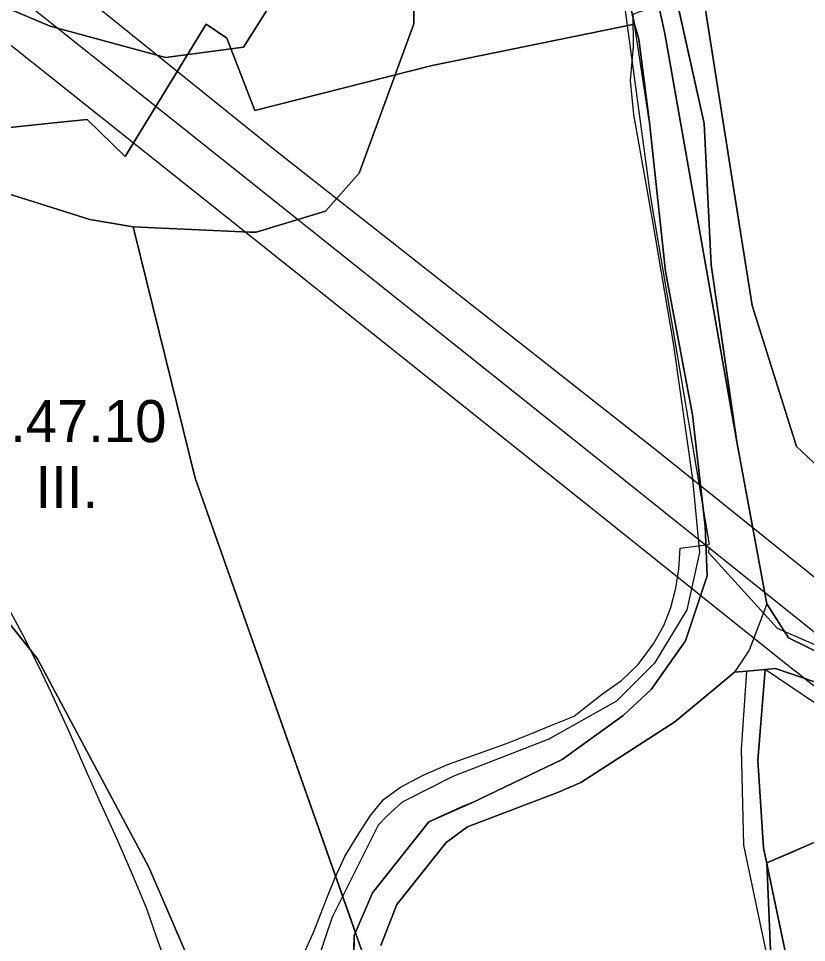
# Model space of a CAD drawing. Extents: x -690419 to -685080, y -987825 to -981190.
# Drawn here: x -687235.5 to -687048.1, y -987168.9 to -986949.2 of the extents above; entities that cross this region are included whole.
import ezdxf

# ---------------------------------------------------------------- set-up
doc = ezdxf.new("R2010")
doc.units = 0
for name, color, linetype in [('BPEJ (S) - hranice', 7, 'Continuous'), ('BPEJ (S) - kód', 7, 'Continuous'), ('BPEJ I-II ochrana', 7, 'Continuous'), ('Elektro VN 35 nadzemní (S)', 7, 'Continuous'), ('OP elektro VN (S)', 7, 'Continuous'), ('Plochy smíšené nezastavěného území všeobecné MU (S)', 7, 'Continuous'), ('Plochy veřejná prostranství všeobecná PU (S)', 7, 'Continuous'), ('Plochy zemědělské všeobecné AU (S)', 7, 'Continuous'), ('Regulační bloky STABILIZOVANÉ (S)', 7, 'Continuous'), ('Spoje - komunikační vedení bez rozlišení provozovanál (S)', 7, 'Continuous'), ('Trasy cykloturistické (S)', 7, 'Continuous'), ('Trasy turistické (S)', 7, 'Continuous'), ('Vodovodní řady přiváděcí (S)', 7, 'Continuous')]:
    doc.layers.add(name, color=color, linetype=linetype)

msp = doc.modelspace()

# ---------------------------------------------------------------- linework, layer by layer
at = {"layer": 'BPEJ (S) - hranice'}
for points in [[(-687151, -987179), (-687193.5, -987058.5), (-687207.88, -987000), (-687208.19, -986998.75), (-687194.34, -986999.37), (-687180.5, -987000), (-687179, -987000), (-687162.5, -986995), (-687154.5, -986986), (-687141.5, -986950.5), (-687141, -986905.5), (-687147, -986860.5), (-687168.5, -986791), (-687205.5, -986705), (-687244, -986635.5)], [(-687244, -986635.5), (-687205.5, -986705), (-687168.5, -986791), (-687147, -986860.5), (-687141, -986905.5), (-687141.5, -986950.5), (-687154.5, -986986), (-687162.5, -986995), (-687179, -987000), (-687180.5, -987000), (-687194.34, -986999.37), (-687208.19, -986998.75), (-687218.5, -986997), (-687242.5, -986989.5)], [(-687273, -986932), (-687228, -986951), (-687200.5, -986958.5), (-687182, -986956), (-687176, -986946.5), (-687178, -986933), (-687195.5, -986898), (-687200.5, -986888.5), (-687256.5, -986707)], [(-687238, -986892.5), (-687195.5, -986898), (-687178, -986933), (-687176, -986946.5), (-687182, -986956), (-687200.5, -986958.5), (-687228, -986951), (-687273, -986932)], [(-686944.5, -986926), (-686946.5, -986962), (-686946.68, -987000), (-686947, -987070), (-686950.5, -987088), (-686967.5, -987086), (-687024.5, -987071), (-687033, -987067.5), (-687050.5, -987051), (-687061, -987017.5), (-687063.76, -987000), (-687074.5, -986932)], [(-687074.5, -986932), (-687063.76, -987000), (-687061, -987017.5), (-687050.5, -987051), (-687033, -987067.5), (-687024.5, -987071), (-687022, -987099), (-687015, -987112), (-686990, -987129), (-686932.5, -987151.5), (-686936.25, -987205.68)], [(-687242.5, -986989.5), (-687218.5, -986997), (-687208.19, -986998.75), (-687207.88, -987000), (-687193.5, -987058.5), (-687151, -987179)], [(-687249, -987079), (-687231, -987101.5), (-687204.5, -987151), (-687189, -987187)], [(-687189, -987187), (-687204.5, -987151), (-687231, -987101.5), (-687249, -987079)], [(-687056.5, -987174.58), (-687057.5, -987150), (-687046, -987145), (-686988.5, -987157), (-686969, -987168.5), (-686950, -987186)], [(-686950, -987186), (-686969, -987168.5), (-686988.5, -987157), (-687046, -987145), (-687057.5, -987150), (-687056.5, -987174.58)]]:
    msp.add_lwpolyline(points, dxfattribs=at)
at = {"layer": 'BPEJ I-II ochrana'}
for p, q in [((-687089, -986950.57), (-687098.46, -986908.8)), ((-687079.35, -986943.19), (-687072.43, -986974.16)), ((-687087.97, -986954.16), (-687089, -986950.57)), ((-687085.46, -986973.92), (-687087.97, -986954.16)), ((-687081.65, -987009.35), (-687085.46, -986973.92)), ((-687072.43, -986974.16), (-687070.74, -987007.79)), ((-687070.74, -987007.79), (-687064.71, -987049.91)), ((-687075.25, -987043.43), (-687081.65, -987009.35)), ((-687072.23, -987069.95), (-687075.25, -987043.43)), ((-687064.71, -987049.91), (-687057.51, -987088.37)), ((-687071.71, -987081.71), (-687072.23, -987069.95)), ((-687076.84, -987097.19), (-687071.71, -987081.71)), ((-687057.51, -987088.37), (-687052.41, -987096.45)), ((-687052.41, -987096.45), (-687043.38, -987100.92)), ((-687085.03, -987108.79), (-687076.84, -987097.19)), ((-687065.23, -987104.62), (-687069.67, -987108.38)), ((-687062.27, -987104.38), (-687065.23, -987104.62)), ((-687063.59, -987122.98), (-687062.27, -987104.38)), ((-687057.95, -987104.02), (-687059.69, -987125.65)), ((-687031.33, -987121.96), (-687057.95, -987104.02)), ((-687091.67, -987114.95), (-687085.03, -987108.79)), ((-687069.67, -987108.38), (-687079.4, -987116.46)), ((-687106.18, -987125.43), (-687091.67, -987114.95)), ((-687079.4, -987116.46), (-687101.73, -987130.92)), ((-687063.04, -987145.76), (-687063.59, -987122.98)), ((-687127.72, -987135.74), (-687106.18, -987125.43)), ((-687059.69, -987125.65), (-687058.33, -987146.42)), ((-687101.73, -987130.92), (-687107.05, -987133.19)), ((-687107.05, -987133.19), (-687128.7, -987141.41)), ((-687137.9, -987140.22), (-687129.74, -987136.48)), ((-687129.74, -987136.48), (-687127.72, -987135.74)), ((-687151.34, -987157.1), (-687137.9, -987140.22)), ((-687128.7, -987141.41), (-687133.81, -987145.13)), ((-687133.81, -987145.13), (-687145.5, -987159.88)), ((-687057.29, -987172.87), (-687063.04, -987145.76)), ((-687058.33, -987146.42), (-687057.48, -987150.46)), ((-687057.5, -987150), (-687051.94, -987147.58)), ((-687057.48, -987150.46), (-687057.5, -987150)), ((-687155.38, -987166.57), (-687151.34, -987157.1)), ((-687145.5, -987159.88), (-687149.31, -987169.64))]:
    msp.add_line(p, q, dxfattribs=at)
for points in [[(-687141, -986905.5), (-687141.5, -986950.5), (-687145.94, -986962.62)], [(-687145.94, -986962.62), (-687154.5, -986986), (-687162.5, -986995), (-687179, -987000), (-687180.5, -987000), (-687194.34, -986999.37), (-687208.19, -986998.75), (-687207.88, -987000), (-687193.5, -987058.5), (-687155.38, -987166.57)], [(-687051.94, -987147.58), (-687046, -987145), (-687033.03, -987147.71)]]:
    msp.add_lwpolyline(points, dxfattribs=at)
at = {"layer": 'Elektro VN 35 nadzemní (S)'}
msp.add_lwpolyline([(-687044.68, -987096.41), (-687089.26, -987060.74), (-687180.2, -986988.23), (-687272.01, -986915.09), (-687345.55, -986856.07), (-687424.59, -986793.57), (-687400.71, -986748.73), (-687400.48, -986748.73), (-687400.48, -986748.81)], dxfattribs=at)
at = {"layer": 'OP elektro VN (S)'}
for points in [[(-688231.26, -985362.69), (-688140.91, -985333.4), (-688050.6, -985304.66), (-687926.78, -985265.47), (-687889.09, -985253.55), (-687783.25, -985486.14), (-687655.15, -985766.87), (-687464.28, -985986.39), (-687075.22, -986433.52), (-686939.38, -986589.57), (-686741.02, -986817.05), (-686769.51, -986926.18), (-686773.44, -986930.55), (-686967.58, -987146.08), (-686995.86, -987122.7), (-687037.52, -987089.1), (-687083.41, -987052.28), (-687174.55, -986980.54), (-687265.93, -986906.92), (-687339.37, -986847.5), (-687412.5, -986789.56), (-687406.22, -986778.12)], [(-687422.93, -986769.17), (-687433.42, -986788.87), (-687434.1, -986790.47), (-687434.49, -986792.16), (-687434.59, -986793.89), (-687434.38, -986795.62), (-687433.88, -986797.28), (-687433.1, -986798.83), (-687432.06, -986800.22), (-687430.8, -986801.41), (-687351.78, -986863.89), (-687278.26, -986922.9), (-687186.43, -986996.05), (-687095.5, -987068.56), (-687050.93, -987104.22), (-687050.91, -987104.23)], [(-687050.91, -987104.23), (-687050.9, -987104.24), (-687008.22, -987138.15), (-686980.45, -987160.36)]]:
    msp.add_lwpolyline(points, dxfattribs=at)
at = {"layer": 'Plochy smíšené nezastavěného území všeobecné MU (S)'}
msp.add_lwpolyline([(-687064.71, -987049.91), (-687081.8, -986952.81), (-687097.31, -986882.03), (-687100.79, -986858.01), (-687105.29, -986824.57), (-687109.25, -986799.46), (-687102.67, -986798.7), (-687068.39, -986793.35), (-687049.96, -986854.98), (-687097.68, -986857.59), (-687097.65, -986861.02), (-687089.57, -986859.96), (-687088.88, -986889.77), (-687086.04, -986905.54), (-687079.35, -986943.19), (-687072.43, -986974.16), (-687070.74, -987007.79)], close=True, dxfattribs=at)
for points in [[(-687238.33, -986902.04), (-687202.07, -986901.51), (-687198.86, -986901.11), (-687195.86, -986900.35), (-687140.12, -986891.8), (-687134.26, -986917.02), (-687098.46, -986908.8), (-687089, -986950.57), (-687125.45, -986958), (-687137.1, -986960.37), (-687179.27, -986971.1), (-687185.91, -986953.93), (-687190.89, -986950.58), (-687210.15, -986982.01), (-687219.17, -986973.2), (-687225.5, -986973.87), (-687238.33, -986975.22)], [(-687052.28, -987175.23), (-687058.33, -987146.42), (-687059.69, -987125.65), (-687057.95, -987104.02), (-687055.46, -987103.82), (-687046.24, -987106.93), (-687031.65, -987113.14), (-687030.67, -987113.56), (-686938.13, -987152.9), (-686933.49, -987154.73), (-686905.86, -987166.25), (-686904.51, -987166.69), (-686905.7, -987172.32)]]:
    msp.add_lwpolyline(points, dxfattribs=at)
at = {"layer": 'Plochy veřejná prostranství všeobecná PU (S)'}
for p, q in [((-687097.31, -986882.03), (-687081.8, -986952.81)), ((-687089, -986950.57), (-687098.46, -986908.8)), ((-687087.97, -986954.16), (-687089, -986950.57)), ((-687085.46, -986973.92), (-687087.97, -986954.16)), ((-687081.8, -986952.81), (-687064.71, -987049.91)), ((-687081.65, -987009.35), (-687085.46, -986973.92)), ((-687075.25, -987043.43), (-687081.65, -987009.35)), ((-687072.23, -987069.95), (-687075.25, -987043.43)), ((-687064.71, -987049.91), (-687057.51, -987088.37)), ((-687071.71, -987081.71), (-687072.23, -987069.95)), ((-687076.84, -987097.19), (-687071.71, -987081.71)), ((-687057.51, -987088.37), (-687052.41, -987096.45)), ((-687052.41, -987096.45), (-687043.38, -987100.92)), ((-687085.03, -987108.79), (-687076.84, -987097.19)), ((-687065.23, -987104.62), (-687069.67, -987108.38)), ((-687062.27, -987104.38), (-687065.23, -987104.62)), ((-687057.95, -987104.02), (-687062.27, -987104.38)), ((-687055.46, -987103.82), (-687057.95, -987104.02)), ((-687046.24, -987106.93), (-687055.46, -987103.82)), ((-687091.67, -987114.95), (-687085.03, -987108.79)), ((-687069.67, -987108.38), (-687079.4, -987116.46)), ((-687106.18, -987125.43), (-687091.67, -987114.95)), ((-687079.4, -987116.46), (-687101.73, -987130.92)), ((-687127.72, -987135.74), (-687106.18, -987125.43)), ((-687101.73, -987130.92), (-687107.05, -987133.19)), ((-687107.05, -987133.19), (-687128.7, -987141.41)), ((-687137.9, -987140.22), (-687129.74, -987136.48)), ((-687129.74, -987136.48), (-687127.72, -987135.74)), ((-687151.34, -987157.1), (-687137.9, -987140.22)), ((-687128.7, -987141.41), (-687133.81, -987145.13)), ((-687133.81, -987145.13), (-687145.5, -987159.88)), ((-687155.68, -987167.27), (-687151.34, -987157.1)), ((-687145.5, -987159.88), (-687149.31, -987169.64)), ((-687156.34, -987207.91), (-687155.68, -987167.27))]:
    msp.add_line(p, q, dxfattribs=at)
at = {"layer": 'Plochy zemědělské všeobecné AU (S)'}
for p, q in [((-687069.67, -987108.38), (-687065.23, -987104.62)), ((-687065.23, -987104.62), (-687062.27, -987104.38)), ((-687062.27, -987104.38), (-687057.95, -987104.02)), ((-687057.95, -987104.02), (-687059.69, -987125.65)), ((-687079.4, -987116.46), (-687069.67, -987108.38)), ((-687101.73, -987130.92), (-687079.4, -987116.46)), ((-687059.69, -987125.65), (-687058.33, -987146.42)), ((-687107.05, -987133.19), (-687101.73, -987130.92)), ((-687128.7, -987141.41), (-687107.05, -987133.19)), ((-687133.81, -987145.13), (-687128.7, -987141.41)), ((-687145.5, -987159.88), (-687133.81, -987145.13)), ((-687058.33, -987146.42), (-687052.28, -987175.23)), ((-687149.31, -987169.64), (-687145.5, -987159.88))]:
    msp.add_line(p, q, dxfattribs=at)
for points in [[(-686936.47, -986938.56), (-686948.57, -987004.84), (-686941.32, -987008.49), (-686941.23, -987025.06), (-686947.38, -987090.16), (-686929.71, -987120.98), (-686926.56, -987106.84), (-686895.85, -987125.85), (-686897.44, -987133.18), (-686903.38, -987161.33), (-686904.48, -987160.91), (-686933.38, -987148.4), (-686935.6, -987147.41), (-687028.95, -987107.87), (-687030.06, -987107.34), (-687031.74, -987106.53), (-687043.38, -987100.92), (-687052.41, -987096.45), (-687057.51, -987088.37), (-687064.71, -987049.91), (-687070.74, -987007.79), (-687072.43, -986974.16), (-687079.35, -986943.19)], [(-687238.33, -986975.22), (-687225.5, -986973.87), (-687219.17, -986973.2), (-687210.15, -986982.01), (-687190.89, -986950.58), (-687185.91, -986953.93), (-687179.27, -986971.1), (-687137.1, -986960.37), (-687125.45, -986958), (-687089, -986950.57), (-687087.97, -986954.16), (-687085.46, -986973.92), (-687081.65, -987009.35), (-687075.25, -987043.43), (-687072.23, -987069.95), (-687071.71, -987081.71), (-687076.84, -987097.19), (-687085.03, -987108.79), (-687091.67, -987114.95), (-687106.18, -987125.43), (-687127.72, -987135.74), (-687129.74, -987136.48), (-687137.9, -987140.22), (-687151.34, -987157.1), (-687155.68, -987167.27), (-687156.34, -987207.91)]]:
    msp.add_lwpolyline(points, dxfattribs=at)
at = {"layer": 'Regulační bloky STABILIZOVANÉ (S)'}
for p, q in [((-687097.31, -986882.03), (-687081.8, -986952.81)), ((-687089, -986950.57), (-687098.46, -986908.8)), ((-687087.97, -986954.16), (-687089, -986950.57)), ((-687085.46, -986973.92), (-687087.97, -986954.16)), ((-687081.8, -986952.81), (-687064.71, -987049.91)), ((-687081.65, -987009.35), (-687085.46, -986973.92)), ((-687075.25, -987043.43), (-687081.65, -987009.35)), ((-687072.23, -987069.95), (-687075.25, -987043.43)), ((-687064.71, -987049.91), (-687057.51, -987088.37)), ((-687071.71, -987081.71), (-687072.23, -987069.95)), ((-687076.84, -987097.19), (-687071.71, -987081.71)), ((-687057.51, -987088.37), (-687052.41, -987096.45)), ((-687052.41, -987096.45), (-687043.38, -987100.92)), ((-687085.03, -987108.79), (-687076.84, -987097.19)), ((-687069.67, -987108.38), (-687065.23, -987104.62)), ((-687065.23, -987104.62), (-687069.67, -987108.38)), ((-687065.23, -987104.62), (-687062.27, -987104.38)), ((-687062.27, -987104.38), (-687065.23, -987104.62)), ((-687062.27, -987104.38), (-687057.95, -987104.02)), ((-687057.95, -987104.02), (-687062.27, -987104.38)), ((-687057.95, -987104.02), (-687059.69, -987125.65)), ((-687055.46, -987103.82), (-687057.95, -987104.02)), ((-687046.24, -987106.93), (-687055.46, -987103.82)), ((-687091.67, -987114.95), (-687085.03, -987108.79)), ((-687079.4, -987116.46), (-687069.67, -987108.38)), ((-687069.67, -987108.38), (-687079.4, -987116.46)), ((-687106.18, -987125.43), (-687091.67, -987114.95)), ((-687101.73, -987130.92), (-687079.4, -987116.46)), ((-687079.4, -987116.46), (-687101.73, -987130.92)), ((-687127.72, -987135.74), (-687106.18, -987125.43)), ((-687059.69, -987125.65), (-687058.33, -987146.42)), ((-687107.05, -987133.19), (-687101.73, -987130.92)), ((-687101.73, -987130.92), (-687107.05, -987133.19)), ((-687128.7, -987141.41), (-687107.05, -987133.19)), ((-687107.05, -987133.19), (-687128.7, -987141.41)), ((-687137.9, -987140.22), (-687129.74, -987136.48)), ((-687129.74, -987136.48), (-687127.72, -987135.74)), ((-687151.34, -987157.1), (-687137.9, -987140.22)), ((-687133.81, -987145.13), (-687128.7, -987141.41)), ((-687128.7, -987141.41), (-687133.81, -987145.13)), ((-687145.5, -987159.88), (-687133.81, -987145.13)), ((-687133.81, -987145.13), (-687145.5, -987159.88)), ((-687058.33, -987146.42), (-687052.28, -987175.23)), ((-687155.68, -987167.27), (-687151.34, -987157.1)), ((-687149.31, -987169.64), (-687145.5, -987159.88)), ((-687145.5, -987159.88), (-687149.31, -987169.64)), ((-687156.34, -987207.91), (-687155.68, -987167.27))]:
    msp.add_line(p, q, dxfattribs=at)
msp.add_lwpolyline([(-687064.71, -987049.91), (-687081.8, -986952.81), (-687097.31, -986882.03), (-687100.79, -986858.01), (-687105.29, -986824.57), (-687109.25, -986799.46), (-687102.67, -986798.7), (-687068.39, -986793.35), (-687049.96, -986854.98), (-687097.68, -986857.59), (-687097.65, -986861.02), (-687089.57, -986859.96), (-687088.88, -986889.77), (-687086.04, -986905.54), (-687079.35, -986943.19), (-687072.43, -986974.16), (-687070.74, -987007.79)], close=True, dxfattribs=at)
for points in [[(-687238.33, -986902.04), (-687202.07, -986901.51), (-687198.86, -986901.11), (-687195.86, -986900.35), (-687140.12, -986891.8), (-687134.26, -986917.02), (-687098.46, -986908.8), (-687089, -986950.57), (-687125.45, -986958), (-687137.1, -986960.37), (-687179.27, -986971.1), (-687185.91, -986953.93), (-687190.89, -986950.58), (-687210.15, -986982.01), (-687219.17, -986973.2), (-687225.5, -986973.87), (-687238.33, -986975.22)], [(-686936.47, -986938.56), (-686948.57, -987004.84), (-686941.32, -987008.49), (-686941.23, -987025.06), (-686947.38, -987090.16), (-686929.71, -987120.98), (-686926.56, -987106.84), (-686895.85, -987125.85), (-686897.44, -987133.18), (-686903.38, -987161.33), (-686904.48, -987160.91), (-686933.38, -987148.4), (-686935.6, -987147.41), (-687028.95, -987107.87), (-687030.06, -987107.34), (-687031.74, -987106.53), (-687043.38, -987100.92), (-687052.41, -987096.45), (-687057.51, -987088.37), (-687064.71, -987049.91), (-687070.74, -987007.79), (-687072.43, -986974.16), (-687079.35, -986943.19)], [(-687238.33, -986975.22), (-687225.5, -986973.87), (-687219.17, -986973.2), (-687210.15, -986982.01), (-687190.89, -986950.58), (-687185.91, -986953.93), (-687179.27, -986971.1), (-687137.1, -986960.37), (-687125.45, -986958), (-687089, -986950.57), (-687087.97, -986954.16), (-687085.46, -986973.92), (-687081.65, -987009.35), (-687075.25, -987043.43), (-687072.23, -987069.95), (-687071.71, -987081.71), (-687076.84, -987097.19), (-687085.03, -987108.79), (-687091.67, -987114.95), (-687106.18, -987125.43), (-687127.72, -987135.74), (-687129.74, -987136.48), (-687137.9, -987140.22), (-687151.34, -987157.1), (-687155.68, -987167.27), (-687156.34, -987207.91)], [(-687052.28, -987175.23), (-687058.33, -987146.42), (-687059.69, -987125.65), (-687057.95, -987104.02), (-687055.46, -987103.82), (-687046.24, -987106.93), (-687031.65, -987113.14), (-687030.67, -987113.56), (-686938.13, -987152.9), (-686933.49, -987154.73), (-686905.86, -987166.25), (-686904.51, -987166.69), (-686905.7, -987172.32)]]:
    msp.add_lwpolyline(points, dxfattribs=at)
at = {"layer": 'Spoje - komunikační vedení bez rozlišení provozovanál (S)'}
for points in [[(-687134.78, -986558.12), (-687128.55, -986596.29), (-687121.87, -986632.23), (-687116.14, -986666.2), (-687116.24, -986675.79), (-687122.7, -986687.4), (-687120.3, -986718.33), (-687117.95, -986746.91), (-687112.46, -986783.6), (-687110.33, -986797.3), (-687107.08, -986821.56), (-687102.66, -986850.7), (-687097.67, -986883.59), (-687093.49, -986909.08), (-687089.93, -986925.78), (-687083.88, -986946.25), (-687087.97, -986947.72), (-687089.42, -986948.25), (-687089.31, -986955.87)], [(-687089.31, -986955.87), (-687090.05, -986963.93), (-687089.23, -986972.08), (-687084.78, -986997), (-687079.71, -987026.92), (-687075.24, -987058.78), (-687073.58, -987076.2), (-687076.54, -987089.84), (-687084.23, -987102.52), (-687093.27, -987111.55), (-687109.34, -987120.61), (-687132.23, -987129.5), (-687144.29, -987135.59), (-687147.81, -987138.83), (-687149.94, -987141.05), (-687160.87, -987162.92), (-687169.9, -987189.61)]]:
    msp.add_lwpolyline(points, dxfattribs=at)
at = {"layer": 'Trasy cykloturistické (S)'}
msp.add_lwpolyline([(-687156.34, -987207.91), (-687155.68, -987167.27), (-687151.34, -987157.1), (-687137.9, -987140.22), (-687127.72, -987135.74), (-687106.18, -987125.43), (-687091.67, -987114.95), (-687085.03, -987108.79), (-687076.84, -987097.19), (-687071.71, -987081.71), (-687072.23, -987069.95), (-687075.25, -987043.43), (-687081.65, -987009.35), (-687085.46, -986973.92), (-687089, -986950.57), (-687098.46, -986908.8)], dxfattribs=at)
at = {"layer": 'Trasy turistické (S)'}
msp.add_lwpolyline([(-687148.24, -986515.1), (-687133.5, -986598.3), (-687124.79, -986663.8), (-687121.11, -986707.42), (-687118.1, -986714.38), (-687115.43, -986735.93), (-687117.23, -986748.83), (-687105.29, -986824.57), (-687097.31, -986882.03), (-687081.8, -986952.81), (-687064.71, -987049.91), (-687057.51, -987088.37), (-687058.74, -987091.61), (-687061.71, -987099.42), (-687065.23, -987104.62), (-687069.67, -987108.38), (-687079.4, -987116.46), (-687101.73, -987130.92), (-687107.05, -987133.19), (-687128.7, -987141.41), (-687133.81, -987145.13), (-687145.5, -987159.88), (-687149.31, -987169.64)], dxfattribs=at)
at = {"layer": 'Vodovodní řady přiváděcí (S)'}
for points in [[(-687071.2, -987074.27), (-687085.19, -986991.22), (-687093.18, -986932.06), (-687097.86, -986909.3), (-687117.8, -986778.74), (-687126.33, -986747.93), (-687155.55, -986523.5), (-687161.37, -986495.96), (-687174.14, -986397.25), (-687179.73, -986373.65), (-687186.14, -986334.24), (-687218.06, -986206.5)], [(-687167.57, -987171.38), (-687165.35, -987166.57), (-687162, -987158.01), (-687160.16, -987153.45), (-687157.86, -987148.45), (-687154.97, -987143.69), (-687151.82, -987138.74), (-687148.7, -987134.96), (-687144.69, -987132.02), (-687139.27, -987129.12), (-687133.24, -987126.54), (-687126.1, -987124), (-687119.43, -987121.62), (-687113.52, -987119.25), (-687108.48, -987117.2), (-687103.35, -987115.11), (-687099.9, -987112.32), (-687096.58, -987109.79), (-687092.08, -987106.64), (-687088.1, -987102.82), (-687084.5, -987097.88), (-687082, -987093.55), (-687080.34, -987089.29), (-687079.14, -987084.71), (-687078.5, -987080.14), (-687078.16, -987075.13), (-687071.4, -987074.26)], [(-686841.2, -987440.61), (-686848.76, -987439.19), (-686903.68, -987413.37), (-686903.65, -987371.15), (-686859.73, -987176.17), (-686880.57, -987166.29), (-686900.65, -987158.08), (-686926.23, -987150.51), (-687054.99, -987094.27), (-687071.39, -987076.19), (-687071.13, -987074.96)], [(-687239.66, -987086.08), (-687234.69, -987095.4), (-687230.82, -987103.1), (-687227.73, -987109.53), (-687223.25, -987119.27), (-687219.68, -987127.5), (-687216.09, -987135.66), (-687212.22, -987144.09), (-687208.75, -987151.98), (-687205.08, -987160.83), (-687202.64, -987167.74), (-687200.94, -987172.56)]]:
    msp.add_lwpolyline(points, dxfattribs=at)

# ---------------------------------------------------------------- texts
at = {"layer": 'BPEJ (S) - kód'}
for s, p in [('7.47.10', (-687244.93, -987049.96)), ('III.', (-687231.43, -987065.65))]:
    msp.add_text(s, height=10, dxfattribs=at).set_placement(p)

doc.saveas('drawing.dxf')
